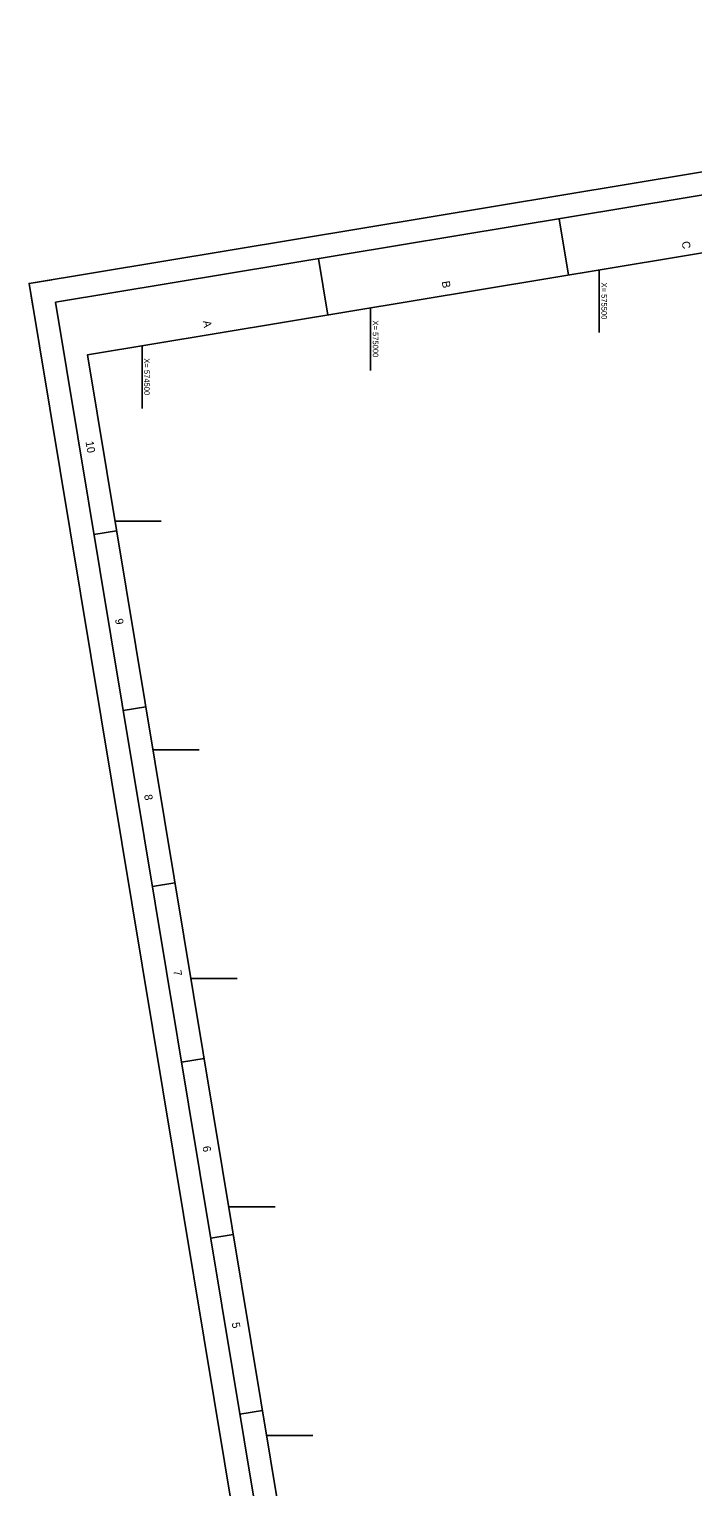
# Model space of a CAD drawing. Extents: x 574253 to 578327, y 864179 to 869076.
# Drawn here: x 574253 to 575705, y 865888 to 869076 of the extents above; entities that cross this region are included whole.
import ezdxf

# ---------------------------------------------------------------- set-up
doc = ezdxf.new("R2010")
doc.units = 0
for name, color, linetype in [('G-ANNO-NPLT', 7, 'Continuous'), ('G-ANNO-TTLB', 7, 'Continuous'), ('V-TOPO-COOR-STAT', 7, 'Continuous')]:
    doc.layers.add(name, color=color, linetype=linetype)

msp = doc.modelspace()

# ---------------------------------------------------------------- linework, layer by layer
at = {"layer": 'G-ANNO-NPLT'}
msp.add_lwpolyline([(577607.4, 869075.9), (578327.2, 864735.2), (574973, 864179), (574253.2, 868519.7)], close=True, dxfattribs=at)
msp.add_lwpolyline([(574302.6, 868527.9), (574253.2, 868519.7), (574261.4, 868470.4)], dxfattribs=at)
at = {"layer": 'G-ANNO-TTLB'}
for p, q in [((575412.3, 868661.2), (575432.7, 868537.9)), ((574886.2, 868574), (574906.6, 868450.7)), ((574395, 867970.5), (574444.3, 867978.7)), ((574458.8, 867585.8), (574508.1, 867593.9)), ((574522.6, 867201), (574571.9, 867209.2)), ((574586.4, 866816.3), (574635.7, 866824.5)), ((574650.2, 866431.5), (574699.5, 866439.7)), ((574714, 866046.8), (574763.3, 866055))]:
    msp.add_line(p, q, dxfattribs=at)
for points in [[(574310.7, 868478.6), (575014.2, 864236.5), (578269.7, 864776.4), (577566.3, 869018.4)], [(578212.2, 864817.5), (577537.4, 868886.9), (574380.5, 868363.4), (575055.3, 864294)]]:
    msp.add_lwpolyline(points, close=True, dxfattribs=at)
at = {"layer": 'V-TOPO-COOR-STAT'}
for p, q in [((575500, 868412.2), (575500, 868549.1)), ((575000, 868329.3), (575000, 868466.2)), ((574500, 868246.4), (574500, 868383.2)), ((574440.8, 868000), (574542.1, 868000)), ((574523.7, 867500), (574625.1, 867500)), ((574606.6, 867000), (574708, 867000)), ((574689.5, 866500), (574790.9, 866500)), ((574772.4, 866000), (574873.8, 866000))]:
    msp.add_line(p, q, dxfattribs=at)

# ---------------------------------------------------------------- texts
at = {"layer": 'G-ANNO-TTLB'}
for s, p in [('C', (575680.1, 868610.7)), ('B', (575155.4, 868523.8)), ('A', (574633, 868437.4)), ('10', (574376.5, 868173.6)), ('9', (574440.9, 867785.4)), ('8', (574504.6, 867400.9)), ('7', (574568.4, 867016.7)), ('6', (574632.2, 866631.9)), ('5', (574696.1, 866246.4))]:
    msp.add_text(s, height=17.5, rotation=279.4155, dxfattribs=at).set_placement(p)
at = {"layer": 'V-TOPO-COOR-STAT'}
for s, p in [('X= 575500', (575504.7, 868521.8)), ('X= 575000', (575004.7, 868438.9)), ('X= 574500', (574504.7, 868356))]:
    msp.add_text(s, height=12, rotation=270, dxfattribs=at).set_placement(p)

doc.saveas('drawing.dxf')
